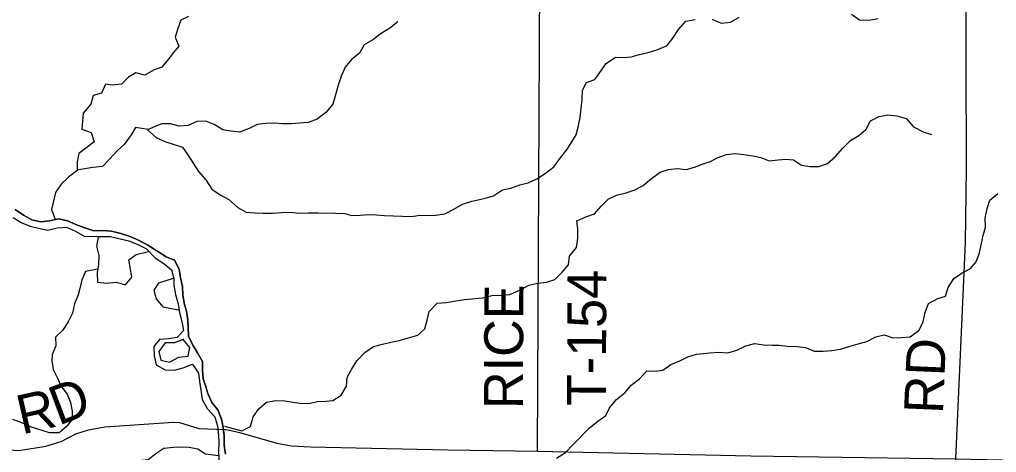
# Model space of a CAD drawing. Extents: x 1985906 to 2277390, y 930619 to 1324581.
# Drawn here: x 2085773 to 2093296, y 1124370 to 1127702 of the extents above; entities that cross this region are included whole.
import ezdxf

# ---------------------------------------------------------------- set-up
doc = ezdxf.new("R2010")
doc.units = 0
for name, color, linetype in [('GM_X_Major_River', 7, 'Continuous'), ('GM_X_Minor_River', 7, 'Continuous'), ('GM_X_Township_Road', 7, 'Continuous'), ('GM_X_Township_Road_Text', 7, 'Continuous')]:
    doc.layers.add(name, color=color, linetype=linetype)

msp = doc.modelspace()

# ---------------------------------------------------------------- linework, layer by layer
at = {"layer": 'GM_X_Major_River'}
for points in [[(2085725.2, 1126178.8), (2085785.7, 1126141.1), (2085854.1, 1126111.4), (2085918.4, 1126095.7), (2085990.8, 1126080.1), (2086062.9, 1126098.6), (2086135.1, 1126105.1), (2086203.5, 1126073.4), (2086272, 1126033.7), (2086377.8, 1126033.2)], [(2085725.2, 1126178.8), (2085785.7, 1126141.1), (2085854.1, 1126111.4), (2085918.4, 1126095.7), (2085990.8, 1126080.1), (2086062.9, 1126098.6), (2086135.1, 1126105.1), (2086203.5, 1126073.4), (2086272, 1126033.7), (2086377.8, 1126033.2)], [(2087204.4, 1124885), (2087188.1, 1124935.9), (2087181.7, 1125000), (2087183.2, 1125070.2), (2087142.7, 1125136.2), (2087106.1, 1125200.2), (2087075.6, 1125266.2), (2087073.1, 1125338.4), (2087068.8, 1125388.5), (2087058.3, 1125456.6), (2087044, 1125508.7), (2087031.5, 1125580.8), (2087027, 1125647), (2087012.6, 1125713.1), (2087002.1, 1125781.3), (2086965.5, 1125851.3), (2086903.2, 1125874.9), (2086830.6, 1125922.7), (2086762.1, 1125964.4), (2086689.6, 1126004.1), (2086625.2, 1126031.8), (2086552.8, 1126055.4), (2086482.5, 1126073), (2086414.2, 1126078.6), (2086346, 1126076.2), (2086275.6, 1126097.9), (2086207.2, 1126123.5), (2086142.8, 1126153.2), (2086076.5, 1126166.9), (2086004.3, 1126152.4), (2085936.2, 1126144), (2085867.8, 1126161.6), (2085803.4, 1126197.3), (2085738.9, 1126239.1)], [(2085738.9, 1126239.1), (2085803.4, 1126197.3), (2085867.8, 1126161.6), (2085936.2, 1126144), (2086004.3, 1126152.4), (2086076.5, 1126166.9), (2086142.8, 1126153.2), (2086207.2, 1126123.5), (2086275.6, 1126097.9), (2086346, 1126076.2), (2086414.2, 1126078.6), (2086482.5, 1126073), (2086552.8, 1126055.4), (2086625.2, 1126031.8), (2086689.6, 1126004.1), (2086762.1, 1125964.4), (2086830.6, 1125922.7), (2086903.2, 1125874.9), (2086965.5, 1125851.3), (2087002.1, 1125781.3), (2087012.6, 1125713.1), (2087027, 1125647), (2087031.5, 1125580.8), (2087044, 1125508.7), (2087058.3, 1125456.6), (2087068.8, 1125388.5), (2087073.1, 1125338.4), (2087075.6, 1125266.2), (2087106.1, 1125200.2), (2087142.7, 1125136.2), (2087183.2, 1125070.2), (2087181.7, 1125000), (2087188.1, 1124935.9), (2087204.4, 1124885)], [(2086375.8, 1126033.2), (2086474.7, 1126032.9), (2086547.1, 1126015.2), (2086615.4, 1125997.6), (2086683.8, 1125971.9), (2086750.2, 1125936.2), (2086816.9, 1125868.4), (2086883.4, 1125824.7), (2086943.9, 1125774.9), (2086960.4, 1125708.8), (2086962.7, 1125658.7), (2086973.2, 1125586.5), (2086993.8, 1125514.4), (2087004.2, 1125446.3), (2087022.7, 1125378.2), (2087035.2, 1125308.1), (2086987.4, 1125255.6), (2086919.2, 1125245.2), (2086851, 1125240.8), (2086807.2, 1125186.3), (2086809.7, 1125114.1), (2086826.2, 1125044), (2086894.6, 1125006.3), (2086964.9, 1125002.8), (2087033, 1125021.2), (2087105.1, 1125049.7), (2087151.7, 1124979.8), (2087160.1, 1124915.6), (2087170.6, 1124849.5), (2087179.1, 1124777.3), (2087217.6, 1124709.4), (2087278.2, 1124645.6), (2087296.8, 1124573.5), (2087305.3, 1124501.3), (2087307.6, 1124449.1), (2087306.5, 1124370.6)], [(2086377.8, 1126033.2), (2086474.7, 1126032.9), (2086547.1, 1126015.2), (2086615.4, 1125997.6), (2086683.8, 1125971.9), (2086750.2, 1125936.2), (2086816.9, 1125868.4), (2086883.4, 1125824.7), (2086943.9, 1125774.9), (2086960.4, 1125708.8), (2086962.7, 1125658.7), (2086973.2, 1125586.5), (2086993.8, 1125514.4), (2087004.2, 1125446.3), (2087022.7, 1125378.2), (2087035.2, 1125308.1), (2086987.4, 1125255.6), (2086919.2, 1125245.2), (2086851, 1125240.8), (2086807.2, 1125186.3), (2086809.7, 1125114.1), (2086826.2, 1125044), (2086894.6, 1125006.3), (2086964.9, 1125002.8), (2087033, 1125021.2), (2087105.1, 1125049.7), (2087151.7, 1124979.8), (2087160.1, 1124915.6), (2087170.6, 1124849.5), (2087179.1, 1124777.3), (2087217.6, 1124709.4), (2087278.2, 1124645.6), (2087296.8, 1124573.5), (2087305.3, 1124501.3), (2087307.6, 1124449.1), (2087306.5, 1124370.3)], [(2087035.6, 1125241.9), (2086967.6, 1125213.4), (2086895.3, 1125212.9), (2086845.6, 1125146.4), (2086862.1, 1125080.4), (2086928.4, 1125064.7), (2087000.4, 1125103.2), (2087072.6, 1125111.7), (2087084.2, 1125178), (2087033, 1125240.8)], [(2087033, 1125240.8), (2086967.6, 1125213.4), (2086895.3, 1125212.9), (2086845.6, 1125146.4), (2086862.1, 1125080.4), (2086928.4, 1125064.7), (2087000.4, 1125103.2), (2087072.6, 1125111.7)], [(2087072.6, 1125111.7), (2087084.2, 1125178), (2087033, 1125240.8)], [(2087204.4, 1124886), (2087204.5, 1124885.8), (2087222.9, 1124823.8), (2087253.5, 1124755.7), (2087300, 1124697.8), (2087328.5, 1124625.8), (2087341, 1124561.7), (2087349.4, 1124497.5), (2087349.9, 1124427.3), (2087358.3, 1124357.2)], [(2087358.3, 1124357.2), (2087349.9, 1124427.3), (2087349.4, 1124497.5), (2087341, 1124561.7), (2087328.5, 1124625.8), (2087300, 1124697.8), (2087253.5, 1124755.7), (2087222.9, 1124823.8), (2087204.4, 1124885)], [(2087224.9, 1124810.1), (2087225, 1124809.7)], [(2087306.5, 1124370.3), (2087310.6, 1124290.7)]]:
    msp.add_lwpolyline(points, dxfattribs=at)
at = {"layer": 'GM_X_Minor_River'}
for points in [[(2087075.2, 1127724.5), (2087015.3, 1127698), (2086991.7, 1127633.6), (2086972.3, 1127565.1), (2086999, 1127497.1), (2086957.3, 1127444.6), (2086917.6, 1127394.1), (2086867.9, 1127335.5), (2086803.9, 1127312.9), (2086738, 1127274.3), (2086669.6, 1127291.8), (2086613.7, 1127259.3), (2086557.9, 1127204.7), (2086485.7, 1127198.1), (2086435.5, 1127203.7), (2086404, 1127135.2), (2086339.9, 1127118.6), (2086322.4, 1127050.3), (2086262.8, 1126981.6), (2086251.9, 1126857), (2086324.3, 1126833.5), (2086347.1, 1126761.4), (2086293.2, 1126720.9), (2086229.4, 1126672.2), (2086215.9, 1126607.9), (2086216.5, 1126539.6), (2086150.7, 1126488.9), (2086093, 1126434.3), (2086051.4, 1126369.8), (2086035.9, 1126303.4), (2086020.5, 1126239.1), (2086048.7, 1126162.3)], [(2086758.7, 1126853.8), (2086824.5, 1126795.3), (2086891, 1126763.7), (2087027.9, 1126720.6), (2087070.5, 1126660.7), (2087109.2, 1126596.8), (2087151.9, 1126532.9), (2087206.7, 1126469.1), (2087253.5, 1126397.2), (2087318.1, 1126353.5), (2087384.7, 1126315.9), (2087453.5, 1126256.2), (2087518, 1126218.6), (2087584.3, 1126213.1), (2087648.5, 1126211.6), (2087720.8, 1126212.1), (2087791, 1126216.7), (2087855.2, 1126219.2), (2087925.5, 1126211.7), (2087997.8, 1126214.3), (2088070, 1126214.9), (2088206.5, 1126211.9), (2088278.8, 1126208.5), (2088331.1, 1126194.8), (2088397.4, 1126197.3), (2088461.6, 1126201.8), (2088521.8, 1126198.3), (2088584, 1126194.8), (2088652.3, 1126191.3), (2088722.6, 1126187.8), (2088790.9, 1126186.4), (2088841, 1126194.8), (2088975.4, 1126195.8), (2089047.6, 1126206.4), (2089117.5, 1126243.1), (2089185.5, 1126279.8), (2089255.5, 1126304.4), (2089305.6, 1126314.8), (2089357.7, 1126327.3), (2089423.7, 1126345.8), (2089493.6, 1126390.5), (2089555.7, 1126403.1), (2089625.7, 1126429.7), (2089689.8, 1126444.2), (2089757.8, 1126474.9), (2089821.7, 1126517.5), (2089887.5, 1126568.2), (2089937.1, 1126634.8), (2089984.7, 1126697.4), (2090018.4, 1126747.9), (2090059.9, 1126814.4), (2090077.4, 1126882.8), (2090090.9, 1126949.2), (2090105.7, 1127085.8), (2090109.1, 1127158), (2090138.7, 1127216.5), (2090204.7, 1127241.1), (2090254.3, 1127311.7), (2090289.9, 1127364.2), (2090363.8, 1127412.9), (2090432, 1127409.4), (2090482.2, 1127413.8), (2090548.3, 1127432.4), (2090614.4, 1127449), (2090688.4, 1127471.7), (2090760.4, 1127502.3), (2090804.1, 1127558.9), (2090847.7, 1127625.4), (2090903.3, 1127690.1), (2090975.4, 1127702.7)], [(2088685.4, 1127684.9), (2088625.6, 1127636.2), (2088557.7, 1127593.6), (2088493.9, 1127544.9), (2088426, 1127506.2), (2088392.4, 1127443.8), (2088330.6, 1127395.1), (2088281, 1127334.5), (2088251.4, 1127270), (2088229.9, 1127205.6), (2088210.4, 1127139.2), (2088185.1, 1127050.7), (2088131.5, 1126986.1), (2088065.7, 1126935.4), (2087995.7, 1126908.8), (2087929.5, 1126904.2), (2087867.3, 1126899.7), (2087797.1, 1126899.2), (2087738.8, 1126904.8), (2087670.6, 1126902.2), (2087604.4, 1126893.7), (2087540.5, 1126863.1), (2087468.4, 1126834.4), (2087400.1, 1126841.9), (2087337.8, 1126853.5), (2087273.2, 1126893.1), (2087206.8, 1126918.7), (2087138.5, 1126918.1), (2087070.6, 1126887.5), (2087002.4, 1126880.9), (2086936, 1126900.5), (2086867.7, 1126898), (2086763.3, 1126856.9)], [(2091107.9, 1127703.7), (2091176.4, 1127674.2), (2091248.6, 1127682.7), (2091314.5, 1127719.4)], [(2092179.4, 1127742.1), (2092242, 1127698.5), (2092314.3, 1127697), (2092386.4, 1127709.6)], [(2087351.1, 1124573.2), (2087417.5, 1124553.6), (2087484, 1124536), (2087552, 1124570.7), (2087571.5, 1124643.2), (2087617.1, 1124705.9), (2087675, 1124756.6), (2087747.2, 1124769.2), (2087815.5, 1124767.7), (2087865.7, 1124760), (2087930.1, 1124750.5), (2088000.4, 1124747), (2088066.6, 1124761.6), (2088134.8, 1124766.1), (2088185, 1124770.6), (2088248.9, 1124811.2), (2088290.5, 1124879.9), (2088296, 1124946.3), (2088329.7, 1125008.8), (2088371.3, 1125075.5), (2088433.1, 1125138.3), (2088498.9, 1125185), (2088567.1, 1125203.6), (2088633.2, 1125220.2), (2088697.4, 1125232.8), (2088767.5, 1125253.4), (2088839.7, 1125272.1), (2088895.5, 1125320.7), (2088913, 1125389.2), (2088928.6, 1125455.6), (2088988.3, 1125518.4), (2089060.6, 1125523), (2089132.7, 1125537.6), (2089200.9, 1125546.2), (2089337.4, 1125559.3), (2089409.6, 1125577.9), (2089481.8, 1125580.5), (2089550.1, 1125587.1), (2089622.1, 1125619.8), (2089694.1, 1125656.5), (2089764.3, 1125673.1), (2089830.5, 1125679.7), (2089896.6, 1125702.3), (2089952.4, 1125757), (2090000.1, 1125813.6), (2090009.6, 1125882.1), (2090061.3, 1125946.8), (2090072.8, 1126019.2), (2090072.2, 1126087.5), (2090065.7, 1126153.8), (2090133.7, 1126182.5), (2090201.8, 1126207.1), (2090251.5, 1126265.8), (2090305.3, 1126320.5), (2090371.4, 1126349.1), (2090443.5, 1126367.8), (2090511.6, 1126390.4), (2090575.6, 1126425.1), (2090639.4, 1126477.8), (2090705.3, 1126526.6), (2090771.4, 1126547.2), (2090837.6, 1126555.7), (2090906, 1126548.2), (2090972.1, 1126564.8), (2091044.2, 1126593.5), (2091094.2, 1126610), (2091146.3, 1126636.5), (2091218.3, 1126663.2), (2091284.5, 1126671.7), (2091350.9, 1126662.2), (2091419.2, 1126652.7), (2091481.6, 1126639.1), (2091546.1, 1126615.5), (2091616.3, 1126622.1), (2091670.5, 1126628.5), (2091732.8, 1126622.9), (2091795.4, 1126581.2), (2091859.7, 1126569.7), (2091928, 1126570.2), (2091996.1, 1126594.8), (2092057.9, 1126647.6), (2092113.7, 1126712.3), (2092171.4, 1126771.1), (2092235.4, 1126809.7), (2092293.2, 1126858.4), (2092326.8, 1126923), (2092392.8, 1126955.6), (2092459, 1126968.2), (2092529.4, 1126960.7), (2092601.9, 1126939.2), (2092656.6, 1126877.3), (2092731.2, 1126837.7), (2092795.6, 1126818.1)], [(2086763.3, 1126856.9), (2086667.2, 1126872.3), (2086633.6, 1126815.9), (2086580.1, 1126739.2), (2086526.3, 1126690.6), (2086466.7, 1126627.9), (2086411, 1126571.3), (2086338.8, 1126562.7), (2086214, 1126541.8)], [(2089907.7, 1124325.7), (2089977.6, 1124370.4), (2090037.4, 1124431.2), (2090160.9, 1124556.7), (2090226.7, 1124611.5), (2090288.6, 1124654.2), (2090316.2, 1124714.7), (2090370, 1124777.4), (2090433.8, 1124828.2), (2090483.5, 1124888.8), (2090547.4, 1124937.6), (2090603.2, 1124998.3), (2090665.4, 1124996.8), (2090727.6, 1125003.3), (2090787.5, 1125045.9), (2090857.6, 1125076.6), (2090919.6, 1125107.3), (2090985.7, 1125127.9), (2091037.9, 1125132.3), (2091088.1, 1125136.7), (2091158.3, 1125143.3), (2091228.6, 1125135.8), (2091296.7, 1125158.4), (2091366.8, 1125191.1), (2091434.9, 1125207.7), (2091503.3, 1125198.2), (2091571.6, 1125196.7), (2091621.8, 1125197.1), (2091686.1, 1125187.5), (2091758.4, 1125186.1), (2091824.8, 1125178.6), (2091893.3, 1125150.9), (2091961.6, 1125149.5), (2092027.8, 1125156), (2092094, 1125164.6), (2092160.1, 1125185.2), (2092230.2, 1125205.8), (2092298.4, 1125224.4), (2092366.4, 1125259.1), (2092430.5, 1125275.7), (2092499, 1125252.1), (2092563.2, 1125254.6), (2092631.4, 1125261.1), (2092701.3, 1125311.9), (2092730.9, 1125376.5), (2092746.4, 1125446.9), (2092772, 1125515.5), (2092844, 1125556.2), (2092904.1, 1125572.8), (2092923.6, 1125639.2), (2092967.3, 1125707.9), (2093033.2, 1125752.6), (2093097.2, 1125785.3), (2093138.9, 1125837.9), (2093164.5, 1125906.4), (2093178.1, 1125966.8), (2093193.5, 1126039.3), (2093211.1, 1126103.7), (2093208.5, 1126172.1), (2093224, 1126246.5), (2093245.6, 1126311), (2093307.4, 1126363.7)], [(2086377.6, 1126027.1), (2086366.2, 1125956.7), (2086382.8, 1125886.6), (2086381.4, 1125818.4), (2086372, 1125754.1), (2086374.6, 1125681.8), (2086444.9, 1125674.3), (2086517.1, 1125680.9), (2086589.6, 1125661.4), (2086637.2, 1125720), (2086628.7, 1125780.1), (2086614, 1125852.3), (2086671.8, 1125892.9), (2086767.7, 1125916.6)], [(2086372.9, 1125782), (2086281.6, 1125763.4), (2086254, 1125699), (2086238.5, 1125632.6), (2086224.9, 1125582.3), (2086197.4, 1125513.8), (2086180, 1125441.5), (2086148.5, 1125375), (2086104.9, 1125308.4), (2086051.2, 1125257.8), (2086051.8, 1125189.6), (2086024.2, 1125125.1), (2086022.7, 1125075), (2086033.3, 1125008.8), (2086061.9, 1124946.8), (2086092.6, 1124882.8), (2086139.3, 1124819), (2086166, 1124754.9), (2086178.6, 1124688.8), (2086179.2, 1124622.6), (2086131.5, 1124568), (2086077.7, 1124521.4), (2086003.4, 1124520.9), (2085858.5, 1124567.9), (2085792, 1124597.5), (2085721.5, 1124623)], [(2086955.8, 1125710.1), (2086844.4, 1125673.4), (2086808.7, 1125619), (2086825.3, 1125552.9), (2086876.1, 1125491), (2086997.1, 1125466.8)], [(2087304.4, 1124343), (2087205.2, 1124357.6), (2087146.6, 1124395.3), (2087078.3, 1124408.8), (2087026.1, 1124410.4), (2086957.8, 1124407.9), (2086885.6, 1124401.3), (2086821.8, 1124358.6), (2086764, 1124314), (2086691.8, 1124305.4), (2086627.8, 1124272.8), (2086564, 1124230.2)]]:
    msp.add_lwpolyline(points, dxfattribs=at)
at = {"layer": 'GM_X_Township_Road'}
for points in [[(2089762.8, 1124379.8), (2089787.1, 1129558.6)], [(2092209.8, 1120531.1), (2092209.5, 1121692.2), (2092217.3, 1121736.3), (2092942.6, 1122625), (2092958.5, 1122663.1), (2092964.3, 1122733.3), (2092984.5, 1124321.7), (2093058.6, 1125984.5), (2093064.5, 1126552.1), (2093060.2, 1128238.8), (2093093.9, 1129501.4)], [(2085479.8, 1124404.8), (2085768.5, 1124385.2), (2085975.1, 1124419.9), (2086093.4, 1124454.3), (2086205.6, 1124512.9), (2086303.8, 1124545.3), (2086430.2, 1124567.7), (2086958, 1124603.5), (2087004.1, 1124599.7), (2087152.8, 1124554), (2087357.6, 1124546.6), (2087393.7, 1124542.7), (2087478.1, 1124520.9), (2087753.4, 1124441.6), (2087867.9, 1124421.9), (2088014.4, 1124414.4), (2089070.3, 1124391.6), (2089242.1, 1124388.7), (2089246.5, 1124388.6)], [(2089246.5, 1124388.6), (2089762.8, 1124379.8), (2091404.8, 1124344.9), (2092984.5, 1124321.7), (2094638.6, 1124284.7), (2096880.7, 1124251.6), (2099621.7, 1124213.8)]]:
    msp.add_lwpolyline(points, dxfattribs=at)

# ---------------------------------------------------------------- texts
at = {"layer": 'GM_X_Township_Road_Text'}
for s, rotation, p in [('T-154', 89.71875, (2090288.1, 1124726.8)), ('RICE', 89.69803, (2089649.3, 1124703.6)), ('RD', 87.53231, (2092883.5, 1124664)), ('D', 20.62922, (2086073.5, 1124575.2)), ('R', 12.87848, (2085791.6, 1124507.8))]:
    msp.add_text(s, height=300, rotation=rotation, dxfattribs=at).set_placement(p)

doc.saveas('drawing.dxf')
